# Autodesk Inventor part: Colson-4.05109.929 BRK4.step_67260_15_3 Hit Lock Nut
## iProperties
Created: 2010-10
Part Number: Colson-4.05109.929 BRK4.step_67260_15_3 Hit Lock Nut
Document SubType Name: Modeling
Designer: Administrator
Density: 7.85 g/cm^3
Material: Steel
Mass: 11.2839 g
Surface Area: 11.927 cm^2
Volume: 1.43743 cm^3
Author: Administrator
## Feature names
1. Base1
